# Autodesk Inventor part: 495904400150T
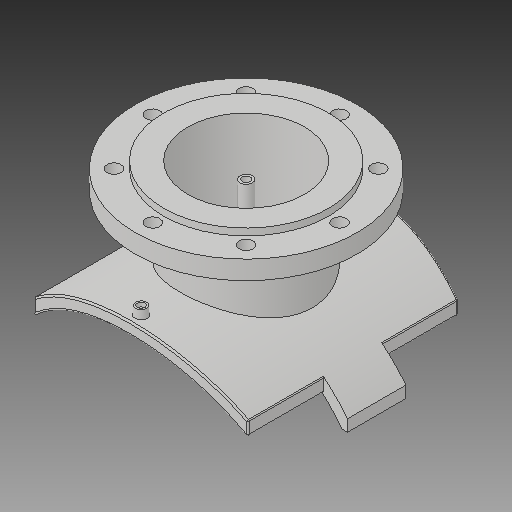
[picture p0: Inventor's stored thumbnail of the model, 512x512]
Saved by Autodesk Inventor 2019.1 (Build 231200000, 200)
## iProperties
Created: 2017-10
Part Number: 495904400150T
Material: Generic
Description: PLASSON FLANGED BRANCH SADDLE 250-400X150
Document SubType Name: Modeling
Designer: KIM
Mass: 2339.99 g
Surface Area: 3251.55 cm^2
Volume: 2339.99 cm^3
Density: 1 g/cm^3
Appearance: Default
Author: KIM
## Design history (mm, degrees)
derived "495904_495903.ipt"
feature "Solid1::495904_495903.ipt"
feature "Solid2::495904_495903.ipt"
tag "TaggingFeature1"
body "Solid1"
other parameters: "d1" = 15, "d2" = 274.5, "d4" = 0, "d6" = 75, "d7" = 0, "d12" = 225.6, "d13" = 14, "d14" = 135, "d16" = 5 deg, "d18" = 4, "d19" = 14, "d20" = 0, "d21" = 3, "d22" = 0, "d23" = 334, "d36" = 135, "d38" = 0, "d39" = 2, "d42" = 212, "d43" = 285, "d44" = 95.2, "d46" = 169.6, "d47" = 16, "d48" = 10.4, "d49" = 83.3, "d51" = 408, "d53" = 0, "d54" = 18, "d57" = 0, "d59" = 360 deg, "d61" = 24, "d63" = 0, "d66" = 119, "d67" = 15, "d68" = 59.5, "d70" = 0, "d71" = 2, "d72" = 305, "d_1" = 212, "B_" = 305, "H_" = 119, "x_" = 15, "D_" = 16, "D_1" = 285, "t_" = 24, "s_" = 18
